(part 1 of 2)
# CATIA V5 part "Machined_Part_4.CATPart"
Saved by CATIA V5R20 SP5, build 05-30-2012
Part number: Macined_Part_4
Source: Unknown
Bounding box of the stored display mesh (mm): x 11486.006 to 11564.501, y -210.178 to 210.176, z 3546.602 to 4547.073
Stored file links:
  C:\Users\rsz0866\Documents\007_CATIA_STEP-Files_and_Test_Models\0001_Machined_Parts_Models\Machined_Part_4.CATPart
  C:\Users\phf1501\Documents\Philshome\LOTAR\LOTAR PMI ASME Data\LOTAR PMI ASME Complex models\LOTAR PMI ASME Complex CATIA Files\LOTAR PMI  ASME Complex CATIA CAD Models\Nacell Support CATIA.CATPart
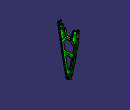
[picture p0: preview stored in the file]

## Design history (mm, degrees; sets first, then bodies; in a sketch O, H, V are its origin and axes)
SpdDefaultsManager1
TTRSSet1
Set1 "MP_4_support"
  DatumSurface1 "OML Surface Section"
  DatumCurve1 "Mid Cutout Sketch"
  DatumCurve2 "Lower Cutout Sketch"
  DatumCurve3 "Main Part Sketch"
  DatumSurface2 "Top cutout surface"
  DatumSurface3 "Top Trim Surface"
  DatumSurface4 "Upper Cutout"
  Plane1: type 2Lines, Element1 edge of DatumCurve1, Element2 edge of DatumCurve2
  Plane2: type 2Lines, Element1 edge of DatumCurve3, Element2 edge of DatumCurve3
  Sketch1 "Center Cutout Sketch" on Plane1, origin (11516.106, 0, 0), H (0, 1, 0), V (0, 0, 1)
    projected line E1 (107.957, 4203.3369) -> (45.82, 4276.09) from edge of DatumCurve1
    projected line E2 (84.7671, 4230.4888) -> (53.4248, 4267.186) from edge of DatumCurve1
    point P1 (107.957, 4203.3369)
    point P2 (45.82, 4276.09)
    projected line E3 (45.82, 4276.09) -> (-45.82, 4276.09) from edge of DatumCurve1
    projected line E4 (34.1105, 4276.09) -> (-34.1105, 4276.09) from edge of DatumCurve1
    point P3 (45.82, 4276.09)
    point P4 (-45.82, 4276.09)
    projected line E5 (-45.82, 4276.09) -> (-107.957, 4203.3369) from edge of DatumCurve1
    projected line E6 (-53.4248, 4267.186) -> (-84.7671, 4230.4888) from edge of DatumCurve1
    point P5 (-45.82, 4276.09)
    point P6 (-107.957, 4203.3369)
    projected curve E7 from edge of DatumCurve1
    projected curve E8 from edge of DatumCurve1
    point P7 (-107.957, 4203.3369)
    point P8 (-82.637, 4059.555)
    projected line E9 (-82.637, 4059.555) -> (82.637, 4059.555) from edge of DatumCurve1
    projected line E10 (-61.4457, 4059.555) -> (61.4457, 4059.555) from edge of DatumCurve1
    point P9 (-82.637, 4059.555)
    point P10 (82.637, 4059.555)
    projected line E11 (67.5561, 3979.545) -> (-67.5561, 3979.545) from edge of DatumCurve2
    projected line E12 (36.6746, 3979.545) -> (-36.6746, 3979.545) from edge of DatumCurve2
    point P11 (67.5561, 3979.545)
    point P12 (-67.5561, 3979.545)
    projected curve E13 from edge of DatumCurve2
    projected curve E14 from edge of DatumCurve2
    point P13 (-67.5561, 3979.545)
    point P14 (-12.3375, 3727.3818)
    projected arc E15 centre (0, 3730.3944) radius 12.7 from (-12.3375, 3727.3818) to (12.3375, 3727.3818) ccw from edge of DatumCurve2
    point P15 (-12.3375, 3727.3818)
    point P16 (12.3375, 3727.3818)
    projected curve E16 from edge of DatumCurve2
    projected curve E17 from edge of DatumCurve2
    point P17 (12.3375, 3727.3818)
    point P18 (67.5561, 3979.545)
    projected curve E18 from edge of DatumCurve1
    projected curve E19 from edge of DatumCurve1
    point P19 (82.637, 4059.555)
    point P20 (107.957, 4203.3369)
    arc A1 centre (-34.1105, 4250.69) radius 25.4 from (-34.1105, 4276.09) to (-53.4248, 4267.186) ccw
    arc A2 centre (-26.8242, 4181.0009) radius 76.2 from (-84.7671, 4230.4888) to (-101.9134, 4168.0377) ccw
    arc A3 centre (-61.4457, 4084.955) radius 25.4 from (-86.4396, 4080.4315) to (-61.4457, 4059.555) ccw
    arc A4 centre (34.1105, 4250.69) radius 25.4 from (34.1105, 4276.09) to (53.4248, 4267.186) cw
    arc A5 centre (26.8242, 4181.0009) radius 76.2 from (84.7671, 4230.4888) to (101.9134, 4168.0377) cw
    arc A6 centre (61.4457, 4084.955) radius 25.4 from (86.4396, 4080.4315) to (61.4457, 4059.555) cw
    arc A7 centre (-36.6746, 3954.145) radius 25.4 from (-36.6746, 3979.545) to (-61.585, 3949.1822) ccw
    arc A8 centre (36.6746, 3954.145) radius 25.4 from (36.6746, 3979.545) to (61.585, 3949.1822) cw
    radius A1 = 25.4
    radius A2 = 76.2
    radius A3 = 25.4
    radius A4 = 25.4
    radius A5 = 76.2
    radius A6 = 25.4
    radius A7 = 25.4
    radius A8 = 25.4
    coincidence: E3 P4, E5 P5, E5 P6, E7 P7, E7 P8, E9 P9, E3 P3, E1 P2, E1 P1, E18 P20, E18 P19, E9 P10, E11 P12, E13 P13, E11 P11, E16 P18, P14 P15, P16 P17
    tangency: A1 E3, A1 E5, A2 E5, A2 E7, A3 E7, A3 E9, A4 E3, A4 E1, A5 E1, A5 E18, A6 E18, A6 E9, A7 E11, A7 E13, A8 E11, A8 E16
  Plane3 "TopPlane": stored without definition
  Offset1 "OML Offset": Offset DatumSurface1, Length 4.318
  Plane4: stored without definition
  Intersect1: ToIntersect1 Plane4, ToIntersect2 DatumSurface3
  Sketch2 "Top Cutout Sketch" on Plane4, origin (279.6175, -1557.6443, -217.9088), H (-0.9843, -0.1767, 0), V (0.0241, -0.1343, 0.9907)
    projected line E1 (-11301.8201, 4764.6026) -> (-11197.9018, 4758.5452) from edge of Intersect1
    projected line E2 (-11405.6729, 4775.6542) -> (-11301.8201, 4764.6026) from edge of Intersect1
    line L1 (-11197.9018, 4758.5452) -> (-11195.8601, 4817.9404)
    line L2 (-11195.8601, 4817.9404) -> (-11399.9073, 4829.8343)
    line L3 (-11399.9073, 4829.8343) -> (-11405.6729, 4775.6542)
    parallelism: L2 E1
    perpendicularity: L3 E2
  Fill1: Boundary Sketch2
  DatumSurface5 "Inside top trim Surface"
Set2 "Hole Support"
  Line1 "AFPO_GROUNDING_FASTENER_FV3": stored without definition
  Line2 "FFPO_FV57": stored without definition
  Line3 "AFPO_GROUNDING_FASTENER_FV2": stored without definition
  Line4 "FFPO_FV58": stored without definition
  Line5 "AFPO_FV45": stored without definition
  Line6 "FFPO_FV59": stored without definition
  Line7 "FFPO_GROUNDING_FASTENER_FV2": stored without definition
  Line8 "AFPO_FV44": stored without definition
  Line9 "AFPO_FV43": stored without definition
  Line10 "FFPO_FV60": stored without definition
  Line11 "AFPO_FV42": stored without definition
  Line12 "FFPO_FV61": stored without definition
  Line13 "AFPO_FV41": stored without definition
  Line14 "FFPO_FV62": stored without definition
  Line15 "AFPO_FV40": stored without definition
  Line16 "FFPO_FV63": stored without definition
  Line17 "AFPO_FV39": stored without definition
  Line18 "FFPO_FV64": stored without definition
  Line19 "FFPO_FV65": stored without definition
  Line20 "AFPO_FV38": stored without definition
  Line21 "AFPO_FV37": stored without definition
  Line22 "FFPO_FV66": stored without definition
  Line23 "AFPO_FV36": stored without definition
  Line24 "FFPO_FV67": stored without definition
  Line25 "FFPO_FV68": stored without definition
  Line26 "AFPO_FV35": stored without definition
  Line27 "AFPO_FV34": stored without definition
  Line28 "FFPO_FV69": stored without definition
  Line29 "AFPO_FV33": stored without definition
  Line30 "FFPO_FV70": stored without definition
  Line31 "FFPO_FV71": stored without definition
  Line32 "AFPO_FV32": stored without definition
  Line33 "AFPO_GROUNDING_FASTENER_FV1": stored without definition
  Line34 "FFPO_FV72": stored without definition
  Line35 "FFPO_FV73": stored without definition
  Line36 "AFPO_FV31": stored without definition
  Line37 "AFPO_FV30": stored without definition
  Line38 "FFPO_FV74": stored without definition
  Line39 "FFPO_FV75": stored without definition
  Line40 to Line78: stored without definition
  Point1 to Point6: stored without definition
  Point7 "Result of Point_6 Fastener Posn Frame 5": stored without definition
  Point8 "Result of Point_5 Fastener Posn Frame 5": stored without definition
Set3 "Pocket stuff"
  DatumSurface6 "Pocket 1 Surface"
  DatumSurface7 "Pocket 2 Surface"
  DatumSurface8 "Pocket 3 Surface"
  DatumSurface9 "Pocket 6 Surface"
  DatumSurface10 "Pocket 8 Surface"
  DatumSurface11 "Pocket 9 Surface"
  DatumSurface12 "Pocket 10 Surface"
  DatumSurface13 "Pocket 11 Surface"
  DatumSurface14 "Pocket 12 Surface"
  DatumSurface15 "Pocket 4 Surface"
  DatumSurface16 "Pocket 5 Surface"
  DatumSurface17 "Pocket 7 Surface"
  DatumSurface18 "Pocket 14 Surface"
Body1 "MP_4_Geo" (main body)
  Pad1: profile DatumCurve3, length 254
  Split1: SplitPlane Offset1
  Split2: SplitPlane DatumSurface2
  Split3: SplitPlane DatumSurface4
  Split4: SplitPlane Plane3
  Pocket1: profile Sketch2, direction (0.175, -0.9751, -0.1364), length 254
  Split5: SplitPlane DatumSurface5
  Mirror1: of the body so far, about Plane2
  Split6: SplitPlane DatumSurface6
  Split7: SplitPlane DatumSurface7
  Split8: SplitPlane DatumSurface8
  Split9: SplitPlane DatumSurface9
  Split10: SplitPlane DatumSurface10
  Split11: SplitPlane DatumSurface11
  Split12: SplitPlane DatumSurface12
  Split13: SplitPlane DatumSurface13
  Fillet1: radius 20.32, on edge [face of Split3 | face of Split3]
  Fillet2: radius 20.32, on edge [face of Mirror1 | face of Mirror1]
  Split14: SplitPlane DatumSurface14
  Fillet3: radius 12.7, on edge [face of Pad1 | face of Mirror1]
  Fillet4: radius 12.7, on edge [face of Split5 | face of Pad1]
  Sketch3 on face of Split5, origin (0, -1117.5755, 4170.8484), H (1, 0, 0), V (0, 0.9659, 0.2588)
    projected curve E1 from edge [face of Split5 | face of Fillet4]
    projected arc E2 centre (4993.4686, 38646.5585) radius 38209.305 from (11496.5567, 994.7214) to (11514.5486, 997.8334) ccw from edge [face of Split5 | face of Split5]
    projected line E3 (11514.5486, 997.8334) -> (11514.5486, 1057.402) from edge [face of Split5 | face of Split5]
    projected line E4 (11486.007, 1057.402) -> (11514.5486, 1057.402) from edge [face of Split5 | face of Split2]
    projected line E5 (11486.007, 1057.402) -> (11486.007, 982.1378) from edge [face of Pad1 | face of Split5]
  Pad2: profile Sketch3, direction (0, -0.2588, 0.9659), length 2.54
  Split15: SplitPlane DatumSurface16
  Split16: SplitPlane DatumSurface17
  Sketch4 on face of Mirror1, origin (0, 1117.5755, 4170.8484), H (-1, 0, 0), V (0, -0.9659, 0.2588)
    projected line E1 (-11486.007, 1057.402) -> (-11514.5486, 1057.402) from edge [face of Mirror1 | face of Mirror1]
    projected line E2 (-11514.5486, 997.8334) -> (-11514.5486, 1057.402) from edge [face of Mirror1 | face of Mirror1]
    projected arc E3 centre (-4993.4686, 38646.5585) radius 38209.305 from (-11514.5486, 997.8334) to (-11496.5567, 994.7214) ccw from edge [face of Mirror1 | face of Mirror1]
    projected curve E4 from edge [face of Mirror1 | face of Fillet3]
    projected line E5 (-11486.007, 982.1378) -> (-11486.007, 1057.402) from edge [face of Pad2 | face of Mirror1]
  Pad3: profile Sketch4, direction (0, 0.2588, 0.9659), length 2.54
  Split17: SplitPlane DatumSurface15
  Body2
    CloseSurface1: CloseElement DatumSurface18
  Remove1: tool Body2
  Pocket2: profile Sketch1, direction (-1, 0, 0), through (limit type 6)
  Sketch5 on {plane type Tangent, Support face of Split1, RefPoint {point type OnSurface, Support face of Split1, RefPoint {point stored without definition}, Length 0, Direction (0, -143.1131, 989.7063)}}, origin (11533.5155, -199.7821, 4491.7645), H (0.9848, 0.1721, 0.0249), V (0, 0.1431, -0.9897)
    point P1 (0, 0)
    intersected point E1 (0, 0) from Line1
    coincidence: E1 P1
  Hole1: placed by Sketch5, at (11533.5155, -199.7821, 4491.7645) direction (0.1739, -0.9746, -0.1409), diameter 9.2964, through (limit type 6)
  Sketch6 on {plane type Tangent, Support face of Split1, RefPoint {point type OnSurface, Support face of Split1, RefPoint {point stored without definition}, Length 0, Direction (0, -151.3494, 988.4803)}}, origin (11533.5335, -193.266, 4448.0114), H (0.9852, 0.1695, 0.026), V (0, 0.1513, -0.9885)
    point P1 (0, 0)
    intersected point E1 (0, 0) from Line3
    coincidence: E1 P1
  Hole2: placed by Sketch6, at (11533.5335, -193.266, 4448.0114) direction (0.1715, -0.9738, -0.1491), diameter 9.2964, through (limit type 6)
  Sketch7 on {plane type Tangent, Support face of Split1, RefPoint {point type OnSurface, Support face of Split1, RefPoint {point stored without definition}, Length 0, Direction (0, -163.5309, 986.5382)}}, origin (11500.5108, -181.5879, 4340.9463), H (0.9864, 0.1623, 0.0269), V (0, 0.1635, -0.9865)
    point P1 (0, 0)
    intersected point E1 (0, 0) from Line7
    coincidence: E1 P1
  Hole3: placed by Sketch7, at (11500.5108, -181.5879, 4340.9463) direction (0.1645, -0.9731, -0.1613), diameter 9.2964, through (limit type 6)
  Sketch8 on {plane type Tangent, Support face of Split1, RefPoint {point type OnSurface, Support face of Split1, RefPoint {point stored without definition}, Length 0, Direction (0, -241.454, 970.4123)}}, origin (11533.7779, -50.159, 3696.5006), H (0.9907, 0.1319, 0.0328), V (0, 0.2415, -0.9704)
    point P1 (0, 0)
    intersected point E1 (0, 0) from Line33
    coincidence: E1 P1
  Hole4: placed by Sketch8, at (11533.7779, -50.159, 3696.5006) direction (0.1359, -0.9614, -0.2392), diameter 9.2964, through (limit type 6)
  Sketch9 on {plane type Tangent, Support face of Mirror1, RefPoint {point type OnSurface, Support face of Mirror1, RefPoint {point stored without definition}, Length 0, Direction (0, -241.454, -970.4123)}}, origin (11533.7779, 50.159, 3696.5006), H (0.9907, -0.1319, 0.0328), V (0, 0.2415, 0.9704)
    point P1 (0, 0)
    intersected point E1 (0, 0) from Line46
    coincidence: E1 P1
  Hole5: placed by Sketch9, at (11533.7779, 50.159, 3696.5006) direction (0.1359, 0.9614, -0.2392), diameter 9.2964, through (limit type 6)
  Sketch10 on {plane type Tangent, Support face of Mirror1, RefPoint {point type OnSurface, Support face of Mirror1, RefPoint {point stored without definition}, Length 0, Direction (0, -163.5309, -986.5382)}}, origin (11500.5108, 181.5879, 4340.9463), H (0.9864, -0.1623, 0.0269), V (0, 0.1635, 0.9865)
    point P1 (0, 0)
    intersected point E1 (0, 0) from Line72
    coincidence: E1 P1
  Hole6: placed by Sketch10, at (11500.5108, 181.5879, 4340.9463) direction (0.1645, 0.9731, -0.1613), diameter 9.2964, through (limit type 6)
  Sketch11 on {plane type Tangent, Support face of Mirror1, RefPoint {point type OnSurface, Support face of Mirror1, RefPoint {point stored without definition}, Length 0, Direction (0, -143.1131, -989.7063)}}, origin (11533.5155, 199.7821, 4491.7645), H (0.9848, -0.1721, 0.0249), V (0, 0.1431, 0.9897)
    point P1 (0, 0)
    intersected point E1 (0, 0) from Line78
    coincidence: E1 P1
  Hole7: placed by Sketch11, at (11533.5155, 199.7821, 4491.7645) direction (0.1739, 0.9746, -0.1409), diameter 9.2964, through (limit type 6)
  Sketch12 on {plane type Tangent, Support face of Mirror1, RefPoint {point type OnSurface, Support face of Mirror1, RefPoint {point stored without definition}, Length 0, Direction (0, -151.3494, -988.4803)}}, origin (11533.5335, 193.266, 4448.0114), H (0.9852, -0.1695, 0.026), V (0, 0.1513, 0.9885)
    point P1 (0, 0)
    intersected point E1 (0, 0) from Line76
    coincidence: E1 P1
  Hole8: placed by Sketch12, at (11533.5335, 193.266, 4448.0114) direction (0.1715, 0.9738, -0.1491), diameter 9.2964, through (limit type 6)
  Sketch13 on face of Split4, origin (11535.2251, -184.7373, 4542.8709), H (0.9967, -0.0122, 0.0803), V (0, 0.9887, 0.1496)
    point P1 (0, 0)
    reference projected point E1 (0, 0) from Point1
    coincidence: E1 P1
  Hole9: placed by Sketch13, at (11535.2251, -184.7373, 4542.8709) direction (0.0812, 0.1492, -0.9855), diameter 6.3119, through (limit type 6)
  Sketch14 on face of Split4, origin (11500.0357, -190.5727, 4539.088), H (0.9967, -0.0122, 0.0803), V (0, 0.9887, 0.1496)
    point P1 (0, 0)
    reference projected point E1 (0, 0) from Point2
    coincidence: E1 P1
  Hole10: placed by Sketch14, at (11500.0357, -190.5727, 4539.088) direction (0.0812, 0.1492, -0.9855), diameter 6.3119, through (limit type 6)
  Sketch15 on face of Mirror1, origin (11535.2251, 184.7373, 4542.8709), H (0.9967, 0.0122, 0.0803), V (0, 0.9887, -0.1496)
    point P1 (0, 0)
    reference projected point E1 (0, 0) from Point4
    coincidence: E1 P1
  Hole11: placed by Sketch15, at (11535.2251, 184.7373, 4542.8709) direction (0.0812, -0.1492, -0.9855), diameter 6.3119, through (limit type 6)
  Sketch16 on face of Mirror1, origin (11500.0357, 190.5727, 4539.088), H (0.9967, 0.0122, 0.0803), V (0, 0.9887, -0.1496)
    point P1 (0, 0)
    reference projected point E1 (0, 0) from Point3
    coincidence: E1 P1
  Hole12: placed by Sketch16, at (11500.0357, 190.5727, 4539.088) direction (0.0812, -0.1492, -0.9855), diameter 6.3119, through (limit type 6)
  Sketch17 on face of Split9, origin (11516.106, -120.65, 4318), H (0, 1, 0), V (0, 0, -1)
    point P1 (0, 0)
    reference projected point E1 (0, 0) from Point5
    coincidence: E1 P1
  Hole13: placed by Sketch17, at (11516.106, -120.65, 4318) direction (1, 0, 0), diameter 6.4008, through (limit type 6)
  Sketch18 on face of Split8, origin (11516.106, 120.65, 4318), H (0, 1, 0), V (0, 0, -1)
    point P1 (0, 0)
    reference projected point E1 (0, 0) from Point6
    coincidence: E1 P1
  Hole14: placed by Sketch18, at (11516.106, 120.65, 4318) direction (1, 0, 0), diameter 6.4008, through (limit type 6)
  Sketch19 on {plane type Tangent, Support face of Split1, RefPoint {point type OnSurface, Support face of Split1, RefPoint {point stored without definition}, Length 0, Direction (0, -144.9294, 989.442)}}, origin (11500.4992, -205.5404, 4490.9343), H (0.9849, 0.1713, 0.0251), V (0, 0.1449, -0.9894)
    point P1 (0, 0)
    intersected point E1 (0, 0) from Line2
    coincidence: E1 P1
  Hole15: placed by Sketch19, at (11500.4992, -205.5404, 4490.9343) direction (0.1732, -0.9745, -0.1427), diameter 7.7089, through (limit type 6)
  Sketch20 on {plane type Tangent, Support face of Split1, RefPoint {point type OnSurface, Support face of Split1, RefPoint {point stored without definition}, Length 0, Direction (0, -153.3155, 988.1773)}}, origin (11500.5026, -198.9361, 4447.1461), H (0.9853, 0.1687, 0.0262), V (0, 0.1533, -0.9882)
    point P1 (0, 0)
    intersected point E1 (0, 0) from Line4
    coincidence: E1 P1
  Hole16: placed by Sketch20, at (11500.5026, -198.9361, 4447.1461) direction (0.1707, -0.9737, -0.1511), diameter 7.7089, through (limit type 6)
  Sketch21 on {plane type Tangent, Support face of Split1, RefPoint {point type OnSurface, Support face of Split1, RefPoint {point stored without definition}, Length 0, Direction (0, -161.8829, 986.81)}}, origin (11533.5577, -184.3459, 4391.7892), H (0.9858, 0.1658, 0.0272), V (0, 0.1619, -0.9868)
    point P1 (0, 0)
    intersected point E1 (0, 0) from Line5
    coincidence: E1 P1
  Hole17: placed by Sketch21, at (11533.5577, -184.3459, 4391.7892) direction (0.168, -0.9728, -0.1596), diameter 7.7089, through (limit type 6)
  Sketch22 on {plane type Tangent, Support face of Split1, RefPoint {point type OnSurface, Support face of Split1, RefPoint {point stored without definition}, Length 0, Direction (0, -164.041, 986.4535)}}, origin (11500.5075, -189.8922, 4390.8825), H (0.9859, 0.165, 0.0274), V (0, 0.164, -0.9865)
    point P1 (0, 0)
    intersected point E1 (0, 0) from Line6
    coincidence: E1 P1
  Hole18: placed by Sketch22, at (11500.5075, -189.8922, 4390.8825) direction (0.1672, -0.9726, -0.1617), diameter 7.7089, through (limit type 6)
  Sketch23 on {plane type Tangent, Support face of Split1, RefPoint {point type OnSurface, Support face of Split1, RefPoint {point stored without definition}, Length 0, Direction (0, -161.7931, 986.8247)}}, origin (11533.5778, -176.1335, 4341.8382), H (0.9863, 0.1631, 0.0267), V (0, 0.1618, -0.9868)
    point P1 (0, 0)
    intersected point E1 (0, 0) from Line8
    coincidence: E1 P1
  Hole19: placed by Sketch23, at (11533.5778, -176.1335, 4341.8382) direction (0.1652, -0.9733, -0.1596), diameter 7.7089, through (limit type 6)
  Sketch24 on {plane type Tangent, Support face of Split1, RefPoint {point type OnSurface, Support face of Split1, RefPoint {point stored without definition}, Length 0, Direction (0, -162.7597, 986.6657)}}, origin (11533.5954, -167.9242, 4291.8914), H (0.9867, 0.1606, 0.0265), V (0, 0.1628, -0.9867)
    point P1 (0, 0)
    intersected point E1 (0, 0) from Line9
    coincidence: E1 P1
  Hole20: placed by Sketch24, at (11533.5954, -167.9242, 4291.8914) direction (0.1628, -0.9735, -0.1606), diameter 7.7089, through (limit type 6)
  Sketch25 on {plane type Tangent, Support face of Split1, RefPoint {point type OnSurface, Support face of Split1, RefPoint {point stored without definition}, Length 0, Direction (0, -164.3356, 986.4045)}}, origin (11500.517, -173.296, 4291.0077), H (0.9868, 0.1598, 0.0266), V (0, 0.1643, -0.9864)
    point P1 (0, 0)
    intersected point E1 (0, 0) from Line10
    coincidence: E1 P1
  Hole21: placed by Sketch25, at (11500.517, -173.296, 4291.0077) direction (0.162, -0.9734, -0.1622), diameter 7.7089, through (limit type 6)
  Sketch26 on {plane type Tangent, Support face of Split1, RefPoint {point type OnSurface, Support face of Split1, RefPoint {point stored without definition}, Length 0, Direction (0, -165.1506, 986.2684)}}, origin (11533.6115, -159.6283, 4241.9652), H (0.987, 0.1583, 0.0265), V (0, 0.1652, -0.9863)
    point P1 (0, 0)
    intersected point E1 (0, 0) from Line11
    coincidence: E1 P1
  Hole22: placed by Sketch26, at (11533.6115, -159.6283, 4241.9652) direction (0.1605, -0.9735, -0.163), diameter 7.7089, through (limit type 6)
  Sketch27 on {plane type Tangent, Support face of Split1, RefPoint {point type OnSurface, Support face of Split1, RefPoint {point stored without definition}, Length 0, Direction (0, -166.6142, 986.0222)}}, origin (11500.5186, -164.9233, 4241.0796), H (0.9872, 0.1575, 0.0266), V (0, 0.1666, -0.986)
    point P1 (0, 0)
    intersected point E1 (0, 0) from Line12
    coincidence: E1 P1
  Hole23: placed by Sketch27, at (11500.5186, -164.9233, 4241.0796) direction (0.1598, -0.9734, -0.1645), diameter 7.7089, through (limit type 6)
  Sketch28 on {plane type Tangent, Support face of Split1, RefPoint {point type OnSurface, Support face of Split1, RefPoint {point stored without definition}, Length 0, Direction (0, -168.4055, 985.7178)}}, origin (11533.6259, -151.1888, 4192.0667), H (0.9874, 0.1561, 0.0267), V (0, 0.1684, -0.9857)
    point P1 (0, 0)
    intersected point E1 (0, 0) from Line13
    coincidence: E1 P1
  Hole24: placed by Sketch28, at (11533.6259, -151.1888, 4192.0667) direction (0.1584, -0.9733, -0.1663), diameter 7.7089, through (limit type 6)
  Sketch29 on {plane type Tangent, Support face of Split1, RefPoint {point type OnSurface, Support face of Split1, RefPoint {point stored without definition}, Length 0, Direction (0, -169.7864, 985.4809)}}, origin (11500.5223, -156.4103, 4191.1734), H (0.9875, 0.1554, 0.0268), V (0, 0.1698, -0.9855)
    point P1 (0, 0)
    intersected point E1 (0, 0) from Line14
    coincidence: E1 P1
  Hole25: placed by Sketch29, at (11500.5223, -156.4103, 4191.1734) direction (0.1577, -0.9732, -0.1677), diameter 7.7089, through (limit type 6)
  Sketch30 on {plane type Tangent, Support face of Split1, RefPoint {point type OnSurface, Support face of Split1, RefPoint {point stored without definition}, Length 0, Direction (0, -172.2768, 985.0486)}}, origin (11533.6404, -142.5689, 4142.202), H (0.9877, 0.154, 0.0269), V (0, 0.1723, -0.985)
    point P1 (0, 0)
    intersected point E1 (0, 0) from Line15
    coincidence: E1 P1
  Hole26: placed by Sketch30, at (11533.6404, -142.5689, 4142.202) direction (0.1563, -0.9729, -0.1702), diameter 7.7089, through (limit type 6)
  Sketch31 on {plane type Tangent, Support face of Split1, RefPoint {point type OnSurface, Support face of Split1, RefPoint {point stored without definition}, Length 0, Direction (0, -173.5999, 984.8163)}}, origin (11500.5259, -147.7209, 4141.3035), H (0.9878, 0.1533, 0.027), V (0, 0.1736, -0.9848)
    point P1 (0, 0)
    intersected point E1 (0, 0) from Line16
    coincidence: E1 P1
  Hole27: placed by Sketch31, at (11500.5259, -147.7209, 4141.3035) direction (0.1556, -0.9728, -0.1715), diameter 7.7089, through (limit type 6)
  Sketch32 on {plane type Tangent, Support face of Split1, RefPoint {point type OnSurface, Support face of Split1, RefPoint {point stored without definition}, Length 0, Direction (0, -176.7535, 984.2552)}}, origin (11533.6539, -133.7389, 4092.3767), H (0.988, 0.152, 0.0273), V (0, 0.1768, -0.9843)
    point P1 (0, 0)
    intersected point E1 (0, 0) from Line17
    coincidence: E1 P1
  Hole28: placed by Sketch32, at (11533.6539, -133.7389, 4092.3767) direction (0.1544, -0.9725, -0.1746), diameter 7.7089, through (limit type 6)
  Sketch33 on {plane type Tangent, Support face of Split1, RefPoint {point type OnSurface, Support face of Split1, RefPoint {point stored without definition}, Length 0, Direction (0, -178.0476, 984.0219)}}, origin (11500.5286, -138.8222, 4091.4663), H (0.9881, 0.1512, 0.0274), V (0, 0.178, -0.984)
    point P1 (0, 0)
    intersected point E1 (0, 0) from Line18
    coincidence: E1 P1
  Hole29: placed by Sketch33, at (11500.5286, -138.8222, 4091.4663) direction (0.1537, -0.9723, -0.1759), diameter 7.7089, through (limit type 6)
  Sketch34 on {plane type Tangent, Support face of Split1, RefPoint {point type OnSurface, Support face of Split1, RefPoint {point stored without definition}, Length 0, Direction (0, -183.284, 983.06)}}, origin (11500.5328, -129.6785, 4041.6701), H (0.9884, 0.1492, 0.0278), V (0, 0.1833, -0.9831)
    point P1 (0, 0)
    intersected point E1 (0, 0) from Line19
    coincidence: E1 P1
  Hole30: placed by Sketch34, at (11500.5328, -129.6785, 4041.6701) direction (0.1518, -0.9717, -0.1812), diameter 7.7089, through (limit type 6)
  Sketch35 on {plane type Tangent, Support face of Split1, RefPoint {point type OnSurface, Support face of Split1, RefPoint {point stored without definition}, Length 0, Direction (0, -181.9836, 983.3016)}}, origin (11533.6674, -124.6646, 4042.5986), H (0.9883, 0.1499, 0.0277), V (0, 0.182, -0.9833)
    point P1 (0, 0)
    intersected point E1 (0, 0) from Line20
    coincidence: E1 P1
  Hole31: placed by Sketch35, at (11533.6674, -124.6646, 4042.5986) direction (0.1524, -0.9718, -0.1799), diameter 7.7089, through (limit type 6)
  Sketch36 on {plane type Tangent, Support face of Split1, RefPoint {point type OnSurface, Support face of Split1, RefPoint {point stored without definition}, Length 0, Direction (0, -188.2022, 982.1303)}}, origin (11533.6814, -115.3027, 3992.8785), H (0.9886, 0.1478, 0.0283), V (0, 0.1882, -0.9821)
    point P1 (0, 0)
    intersected point E1 (0, 0) from Line21
    coincidence: E1 P1
  Hole32: placed by Sketch36, at (11533.6814, -115.3027, 3992.8785) direction (0.1504, -0.971, -0.1861), diameter 7.7089, through (limit type 6)
  Sketch37 on {plane type Tangent, Support face of Split1, RefPoint {point type OnSurface, Support face of Split1, RefPoint {point stored without definition}, Length 0, Direction (0, -189.4221, 981.8957)}}, origin (11500.5367, -120.4291, 3992.8835), H (0.9887, 0.1471, 0.0284), V (0, 0.1894, -0.9819)
    point P1 (0, 0)
    intersected point E1 (0, 0) from Line22
    coincidence: E1 P1
  Hole33: placed by Sketch37, at (11500.5367, -120.4291, 3992.8835) direction (0.1498, -0.9708, -0.1873), diameter 7.7089, through (limit type 6)
  Sketch38 on {plane type Tangent, Support face of Split1, RefPoint {point type OnSurface, Support face of Split1, RefPoint {point stored without definition}, Length 0, Direction (0, -195.6636, 980.6711)}}, origin (11533.6954, -105.5966, 3943.2297), H (0.9889, 0.1455, 0.029), V (0, 0.1957, -0.9807)
    point P1 (0, 0)
    intersected point E1 (0, 0) from Line23
    coincidence: E1 P1
  Hole34: placed by Sketch38, at (11533.6954, -105.5966, 3943.2297) direction (0.1483, -0.9698, -0.1935), diameter 7.7089, through (limit type 6)
  Sketch39 on {plane type Tangent, Support face of Split1, RefPoint {point type OnSurface, Support face of Split1, RefPoint {point stored without definition}, Length 0, Direction (0, -196.4609, 980.5117)}}, origin (11500.5392, -111.257, 3946.2153), H (0.989, 0.145, 0.029), V (0, 0.1965, -0.9805)
    point P1 (0, 0)
    intersected point E1 (0, 0) from Line24
    coincidence: E1 P1
  Hole35: placed by Sketch39, at (11500.5392, -111.257, 3946.2153) direction (0.1479, -0.9697, -0.1943), diameter 7.7089, through (limit type 6)
  Sketch40 on {plane type Tangent, Support face of Split1, RefPoint {point type OnSurface, Support face of Split1, RefPoint {point stored without definition}, Length 0, Direction (0, -204.5244, 978.8615)}}, origin (11533.7109, -95.4795, 3893.6695), H (0.9893, 0.1429, 0.0299), V (0, 0.2045, -0.9789)
    point P1 (0, 0)
    intersected point E1 (0, 0) from Line26
    coincidence: E1 P1
  Hole36: placed by Sketch40, at (11533.7109, -95.4795, 3893.6695) direction (0.146, -0.9684, -0.2023), diameter 7.7089, through (limit type 6)
  Sketch41 on {plane type Tangent, Support face of Split1, RefPoint {point type OnSurface, Support face of Split1, RefPoint {point stored without definition}, Length 0, Direction (0, -204.7685, 978.8104)}}, origin (11500.5433, -101.7214, 3899.6256), H (0.9893, 0.1426, 0.0298), V (0, 0.2048, -0.9788)
    point P1 (0, 0)
    intersected point E1 (0, 0) from Line25
    coincidence: E1 P1
  Hole37: placed by Sketch41, at (11500.5433, -101.7214, 3899.6256) direction (0.1457, -0.9684, -0.2026), diameter 7.7089, through (limit type 6)
  Sketch42 on {plane type Tangent, Support face of Split1, RefPoint {point type OnSurface, Support face of Split1, RefPoint {point stored without definition}, Length 0, Direction (0, -214.7234, 976.6749)}}, origin (11533.7295, -84.8777, 3844.2167), H (0.9897, 0.1401, 0.0308), V (0, 0.2147, -0.9767)
    point P1 (0, 0)
    intersected point E1 (0, 0) from Line27
    coincidence: E1 P1
  Hole38: placed by Sketch42, at (11533.7295, -84.8777, 3844.2167) direction (0.1435, -0.9666, -0.2125), diameter 7.7089, through (limit type 6)
  Sketch43 on {plane type Tangent, Support face of Split1, RefPoint {point type OnSurface, Support face of Split1, RefPoint {point stored without definition}, Length 0, Direction (0, -214.3624, 976.7542)}}, origin (11500.5481, -91.7591, 3853.1309), H (0.9897, 0.14, 0.0307), V (0, 0.2144, -0.9768)
    point P1 (0, 0)
    intersected point E1 (0, 0) from Line28
    coincidence: E1 P1
  Hole39: placed by Sketch43, at (11500.5481, -91.7591, 3853.1309) direction (0.1434, -0.9667, -0.2121), diameter 7.7089, through (limit type 6)
  Sketch44 on {plane type Tangent, Support face of Split1, RefPoint {point type OnSurface, Support face of Split1, RefPoint {point stored without definition}, Length 0, Direction (0, -224.7151, 974.4245)}}, origin (11533.7466, -73.7581, 3794.8771), H (0.99, 0.1372, 0.0316), V (0, 0.2247, -0.9744)
    point P1 (0, 0)
    intersected point E1 (0, 0) from Line29
    coincidence: E1 P1
  Hole40: placed by Sketch44, at (11533.7466, -73.7581, 3794.8771) direction (0.1408, -0.9647, -0.2225), diameter 7.7089, through (limit type 6)
  Sketch45 on {plane type Tangent, Support face of Split1, RefPoint {point type OnSurface, Support face of Split1, RefPoint {point stored without definition}, Length 0, Direction (0, -223.9493, 974.6008)}}, origin (11500.5521, -81.3346, 3806.738), H (0.99, 0.1373, 0.0316), V (0, 0.2239, -0.9746)
    point P1 (0, 0)
    intersected point E1 (0, 0) from Line30
    coincidence: E1 P1
  Hole41: placed by Sketch45, at (11500.5521, -81.3346, 3806.738) direction (0.1409, -0.9649, -0.2217), diameter 7.7089, through (limit type 6)
  Sketch46 on {plane type Tangent, Support face of Split1, RefPoint {point type OnSurface, Support face of Split1, RefPoint {point stored without definition}, Length 0, Direction (0, -233.3083, 972.4028)}}, origin (11533.7634, -62.1656, 3745.6401), H (0.9904, 0.1344, 0.0323), V (0, 0.2333, -0.9724)
    point P1 (0, 0)
    intersected point E1 (0, 0) from Line32
    coincidence: E1 P1
  Hole42: placed by Sketch46, at (11533.7634, -62.1656, 3745.6401) direction (0.1382, -0.9631, -0.2311), diameter 7.7089, through (limit type 6)
  Sketch47 on {plane type Tangent, Support face of Split1, RefPoint {point type OnSurface, Support face of Split1, RefPoint {point stored without definition}, Length 0, Direction (0, -232.2993, 972.6444)}}, origin (11500.5561, -70.4796, 3760.4384), H (0.9904, 0.1348, 0.0322), V (0, 0.2323, -0.9726)
    point P1 (0, 0)
    intersected point E1 (0, 0) from Line31
    coincidence: E1 P1
  Hole43: placed by Sketch47, at (11500.5561, -70.4796, 3760.4384) direction (0.1385, -0.9633, -0.2301), diameter 7.7089, through (limit type 6)
  Sketch48 on {plane type Tangent, Support face of Split1, RefPoint {point type OnSurface, Support face of Split1, RefPoint {point stored without definition}, Length 0, Direction (0, -239.7025, 970.8464)}}, origin (11500.5607, -59.2543, 3714.2229), H (0.9907, 0.1324, 0.0327), V (0, 0.2397, -0.9708)
    point P1 (0, 0)
    intersected point E1 (0, 0) from Line34
    coincidence: E1 P1
  Hole44: placed by Sketch48, at (11500.5607, -59.2543, 3714.2229) direction (0.1364, -0.9618, -0.2375), diameter 7.7089, through (limit type 6)
  Sketch49 on {plane type Tangent, Support face of Split1, RefPoint {point type OnSurface, Support face of Split1, RefPoint {point stored without definition}, Length 0, Direction (0, -248.3602, 968.6678)}}, origin (11500.5648, -47.6608, 3668.1043), H (0.9909, 0.1302, 0.0334), V (0, 0.2484, -0.9687)
    point P1 (0, 0)
    intersected point E1 (0, 0) from Line35
    coincidence: E1 P1
  Hole45: placed by Sketch49, at (11500.5648, -47.6608, 3668.1043) direction (0.1344, -0.9599, -0.2461), diameter 7.7089, through (limit type 6)
  Sketch50 on {plane type Tangent, Support face of Split1, RefPoint {point type OnSurface, Support face of Split1, RefPoint {point stored without definition}, Length 0, Direction (0, -251.4453, 967.8715)}}, origin (11533.7929, -37.6908, 3647.4847), H (0.991, 0.1295, 0.0336), V (0, 0.2514, -0.9679)
    point P1 (0, 0)
    intersected point E1 (0, 0) from Line36
    coincidence: E1 P1
  Hole46: placed by Sketch50, at (11533.7929, -37.6908, 3647.4847) direction (0.1338, -0.9592, -0.2492), diameter 7.7089, through (limit type 6)
  Sketch51 on {plane type Tangent, Support face of Split1, RefPoint {point type OnSurface, Support face of Split1, RefPoint {point stored without definition}, Length 0, Direction (0, -251.0059, 967.9856)}}, origin (11500.5667, -35.7169, 3622.0475), H (0.991, 0.1292, 0.0335), V (0, 0.251, -0.968)
    point P1 (0, 0)
    intersected point E1 (0, 0) from Line38
    coincidence: E1 P1
  Hole47: placed by Sketch51, at (11500.5667, -35.7169, 3622.0475) direction (0.1335, -0.9593, -0.2488), diameter 7.7089, through (limit type 6)
  Sketch52 on {plane type Tangent, Support face of Split1, RefPoint {point type OnSurface, Support face of Split1, RefPoint {point stored without definition}, Length 0, Direction (0, -249.9188, 968.2668)}}, origin (11533.7956, -24.9971, 3598.474), H (0.9911, 0.1291, 0.0333), V (0, 0.2499, -0.9683)
    point P1 (0, 0)
    intersected point E1 (0, 0) from Line37
    coincidence: E1 P1
  Hole48: placed by Sketch52, at (11533.7956, -24.9971, 3598.474) direction (0.1333, -0.9596, -0.2477), diameter 7.7089, through (limit type 6)
  Sketch53 on {plane type Tangent, Support face of Split1, RefPoint {point type OnSurface, Support face of Split1, RefPoint {point stored without definition}, Length 0, Direction (0, -249.4488, 968.388)}}, origin (11500.5675, -23.8047, 3575.9634), H (0.9911, 0.1289, 0.0332), V (0, 0.2494, -0.9684)
    point P1 (0, 0)
    intersected point E1 (0, 0) from Line39
    coincidence: E1 P1
  Hole49: placed by Sketch53, at (11500.5675, -23.8047, 3575.9634) direction (0.1331, -0.9598, -0.2472), diameter 7.7089, through (limit type 6)
  Sketch54 on {plane type Tangent, Support face of Mirror1, RefPoint {point type OnSurface, Support face of Mirror1, RefPoint {point stored without definition}, Length 0, Direction (0, -249.4488, -968.388)}}, origin (11500.5675, 23.8047, 3575.9634), H (0.9911, -0.1289, 0.0332), V (0, 0.2494, 0.9684)
    point P1 (0, 0)
    intersected point E1 (0, 0) from Line40
    coincidence: E1 P1
  Hole50: placed by Sketch54, at (11500.5675, 23.8047, 3575.9634) direction (0.1331, 0.9598, -0.2472), diameter 7.7089, through (limit type 6)
  Sketch55 on {plane type Tangent, Support face of Mirror1, RefPoint {point type OnSurface, Support face of Mirror1, RefPoint {point stored without definition}, Length 0, Direction (0, -249.9188, -968.2668)}}, origin (11533.7956, 24.9971, 3598.474), H (0.9911, -0.1291, 0.0333), V (0, 0.2499, 0.9683)
    point P1 (0, 0)
    intersected point E1 (0, 0) from Line42
    coincidence: E1 P1
  Hole51: placed by Sketch55, at (11533.7956, 24.9971, 3598.474) direction (0.1333, 0.9596, -0.2477), diameter 7.7089, through (limit type 6)
  Sketch56 on {plane type Tangent, Support face of Mirror1, RefPoint {point type OnSurface, Support face of Mirror1, RefPoint {point stored without definition}, Length 0, Direction (0, -251.0059, -967.9856)}}, origin (11500.5667, 35.7169, 3622.0475), H (0.991, -0.1292, 0.0335), V (0, 0.251, 0.968)
    point P1 (0, 0)
    intersected point E1 (0, 0) from Line41
    coincidence: E1 P1
  Hole52: placed by Sketch56, at (11500.5667, 35.7169, 3622.0475) direction (0.1335, 0.9593, -0.2488), diameter 7.7089, through (limit type 6)
  Sketch57 on {plane type Tangent, Support face of Mirror1, RefPoint {point type OnSurface, Support face of Mirror1, RefPoint {point stored without definition}, Length 0, Direction (0, -251.4453, -967.8715)}}, origin (11533.7929, 37.6908, 3647.4847), H (0.991, -0.1295, 0.0336), V (0, 0.2514, 0.9679)
    point P1 (0, 0)
    intersected point E1 (0, 0) from Line43
    coincidence: E1 P1
  Hole53: placed by Sketch57, at (11533.7929, 37.6908, 3647.4847) direction (0.1338, 0.9592, -0.2492), diameter 7.7089, through (limit type 6)
  Sketch58 on {plane type Tangent, Support face of Mirror1, RefPoint {point type OnSurface, Support face of Mirror1, RefPoint {point stored without definition}, Length 0, Direction (0, -248.3602, -968.6678)}}, origin (11500.5648, 47.6608, 3668.1043), H (0.9909, -0.1302, 0.0334), V (0, 0.2484, 0.9687)
    point P1 (0, 0)
    intersected point E1 (0, 0) from Line44
    coincidence: E1 P1
  Hole54: placed by Sketch58, at (11500.5648, 47.6608, 3668.1043) direction (0.1344, 0.9599, -0.2461), diameter 7.7089, through (limit type 6)
  Sketch59 on {plane type Tangent, Support face of Mirror1, RefPoint {point type OnSurface, Support face of Mirror1, RefPoint {point stored without definition}, Length 0, Direction (0, -239.7025, -970.8464)}}, origin (11500.5607, 59.2543, 3714.2229), H (0.9907, -0.1324, 0.0327), V (0, 0.2397, 0.9708)
    point P1 (0, 0)
    intersected point E1 (0, 0) from Line45
    coincidence: E1 P1
  Hole55: placed by Sketch59, at (11500.5607, 59.2543, 3714.2229) direction (0.1364, 0.9618, -0.2375), diameter 7.7089, through (limit type 6)
  Sketch60 on {plane type Tangent, Support face of Mirror1, RefPoint {point type OnSurface, Support face of Mirror1, RefPoint {point stored without definition}, Length 0, Direction (0, -232.2993, -972.6444)}}, origin (11500.5561, 70.4796, 3760.4384), H (0.9904, -0.1348, 0.0322), V (0, 0.2323, 0.9726)
    point P1 (0, 0)
    intersected point E1 (0, 0) from Line48
    coincidence: E1 P1
  Hole56: placed by Sketch60, at (11500.5561, 70.4796, 3760.4384) direction (0.1385, 0.9633, -0.2301), diameter 7.7089, through (limit type 6)
  Sketch61 on {plane type Tangent, Support face of Mirror1, RefPoint {point type OnSurface, Support face of Mirror1, RefPoint {point stored without definition}, Length 0, Direction (0, -233.3083, -972.4028)}}, origin (11533.7634, 62.1656, 3745.6401), H (0.9904, -0.1344, 0.0323), V (0, 0.2333, 0.9724)
    point P1 (0, 0)
    intersected point E1 (0, 0) from Line47
    coincidence: E1 P1
  Hole57: placed by Sketch61, at (11533.7634, 62.1656, 3745.6401) direction (0.1382, 0.9631, -0.2311), diameter 7.7089, through (limit type 6)
  Sketch62 on {plane type Tangent, Support face of Mirror1, RefPoint {point type OnSurface, Support face of Mirror1, RefPoint {point stored without definition}, Length 0, Direction (0, -224.7151, -974.4245)}}, origin (11533.7466, 73.7581, 3794.8771), H (0.99, -0.1372, 0.0316), V (0, 0.2247, 0.9744)
    point P1 (0, 0)
    intersected point E1 (0, 0) from Line50
    coincidence: E1 P1
  Hole58: placed by Sketch62, at (11533.7466, 73.7581, 3794.8771) direction (0.1408, 0.9647, -0.2225), diameter 7.7089, through (limit type 6)
  Sketch63 on {plane type Tangent, Support face of Mirror1, RefPoint {point type OnSurface, Support face of Mirror1, RefPoint {point stored without definition}, Length 0, Direction (0, -223.9493, -974.6008)}}, origin (11500.5521, 81.3346, 3806.738), H (0.99, -0.1373, 0.0316), V (0, 0.2239, 0.9746)
    point P1 (0, 0)
    intersected point E1 (0, 0) from Line49
    coincidence: E1 P1
  Hole59: placed by Sketch63, at (11500.5521, 81.3346, 3806.738) direction (0.1409, 0.9649, -0.2217), diameter 7.7089, through (limit type 6)
  Sketch64 on {plane type Tangent, Support face of Mirror1, RefPoint {point type OnSurface, Support face of Mirror1, RefPoint {point stored without definition}, Length 0, Direction (0, -214.3624, -976.7542)}}, origin (11500.5481, 91.7591, 3853.1309), H (0.9897, -0.14, 0.0307), V (0, 0.2144, 0.9768)
    point P1 (0, 0)
    intersected point E1 (0, 0) from Line51
    coincidence: E1 P1
  Hole60: placed by Sketch64, at (11500.5481, 91.7591, 3853.1309) direction (0.1434, 0.9667, -0.2121), diameter 7.7089, through (limit type 6)
  Sketch65 on {plane type Tangent, Support face of Mirror1, RefPoint {point type OnSurface, Support face of Mirror1, RefPoint {point stored without definition}, Length 0, Direction (0, -214.7234, -976.6749)}}, origin (11533.7295, 84.8777, 3844.2167), H (0.9897, -0.1401, 0.0308), V (0, 0.2147, 0.9767)
    point P1 (0, 0)
    intersected point E1 (0, 0) from Line52
    coincidence: E1 P1
  Hole61: placed by Sketch65, at (11533.7295, 84.8777, 3844.2167) direction (0.1435, 0.9666, -0.2125), diameter 7.7089, through (limit type 6)
  Sketch66 on {plane type Tangent, Support face of Mirror1, RefPoint {point type OnSurface, Support face of Mirror1, RefPoint {point stored without definition}, Length 0, Direction (0, -204.7685, -978.8104)}}, origin (11500.5433, 101.7214, 3899.6256), H (0.9893, -0.1426, 0.0298), V (0, 0.2048, 0.9788)
    point P1 (0, 0)
    intersected point E1 (0, 0) from Line54
    coincidence: E1 P1
  Hole62: placed by Sketch66, at (11500.5433, 101.7214, 3899.6256) direction (0.1457, 0.9684, -0.2026), diameter 7.7089, through (limit type 6)
  Sketch67 on {plane type Tangent, Support face of Mirror1, RefPoint {point type OnSurface, Support face of Mirror1, RefPoint {point stored without definition}, Length 0, Direction (0, -204.5244, -978.8615)}}, origin (11533.7109, 95.4795, 3893.6695), H (0.9893, -0.1429, 0.0299), V (0, 0.2045, 0.9789)
    point P1 (0, 0)
    intersected point E1 (0, 0) from Line53
    coincidence: E1 P1
  Hole63: placed by Sketch67, at (11533.7109, 95.4795, 3893.6695) direction (0.146, 0.9684, -0.2023), diameter 7.7089, through (limit type 6)
  Sketch68 on {plane type Tangent, Support face of Mirror1, RefPoint {point type OnSurface, Support face of Mirror1, RefPoint {point stored without definition}, Length 0, Direction (0, -196.4609, -980.5117)}}, origin (11500.5392, 111.257, 3946.2153), H (0.989, -0.145, 0.029), V (0, 0.1965, 0.9805)
    point P1 (0, 0)
    intersected point E1 (0, 0) from Line55
    coincidence: E1 P1
  Hole64: placed by Sketch68, at (11500.5392, 111.257, 3946.2153) direction (0.1479, 0.9697, -0.1943), diameter 7.7089, through (limit type 6)
  Sketch69 on {plane type Tangent, Support face of Mirror1, RefPoint {point type OnSurface, Support face of Mirror1, RefPoint {point stored without definition}, Length 0, Direction (0, -195.6636, -980.6711)}}, origin (11533.6954, 105.5966, 3943.2297), H (0.9889, -0.1455, 0.029), V (0, 0.1957, 0.9807)
    point P1 (0, 0)
    intersected point E1 (0, 0) from Line56
    coincidence: E1 P1
  Hole65: placed by Sketch69, at (11533.6954, 105.5966, 3943.2297) direction (0.1483, 0.9698, -0.1935), diameter 7.7089, through (limit type 6)
  Sketch70 on {plane type Tangent, Support face of Mirror1, RefPoint {point type OnSurface, Support face of Mirror1, RefPoint {point stored without definition}, Length 0, Direction (0, -189.4221, -981.8957)}}, origin (11500.5367, 120.4291, 3992.8835), H (0.9887, -0.1471, 0.0284), V (0, 0.1894, 0.9819)
    point P1 (0, 0)
    intersected point E1 (0, 0) from Line57
    coincidence: E1 P1
  Hole66: placed by Sketch70, at (11500.5367, 120.4291, 3992.8835) direction (0.1498, 0.9708, -0.1873), diameter 7.7089, through (limit type 6)
  Sketch71 on {plane type Tangent, Support face of Mirror1, RefPoint {point type OnSurface, Support face of Mirror1, RefPoint {point stored without definition}, Length 0, Direction (0, -188.2022, -982.1303)}}, origin (11533.6814, 115.3027, 3992.8785), H (0.9886, -0.1478, 0.0283), V (0, 0.1882, 0.9821)
    point P1 (0, 0)
    intersected point E1 (0, 0) from Line58
    coincidence: E1 P1
  Hole67: placed by Sketch71, at (11533.6814, 115.3027, 3992.8785) direction (0.1504, 0.971, -0.1861), diameter 7.7089, through (limit type 6)
  Sketch72 on {plane type Tangent, Support face of Mirror1, RefPoint {point type OnSurface, Support face of Mirror1, RefPoint {point stored without definition}, Length 0, Direction (0, -183.284, -983.06)}}, origin (11500.5328, 129.6785, 4041.6701), H (0.9884, -0.1492, 0.0278), V (0, 0.1833, 0.9831)
    point P1 (0, 0)
    intersected point E1 (0, 0) from Line60
    coincidence: E1 P1
  Hole68: placed by Sketch72, at (11500.5328, 129.6785, 4041.6701) direction (0.1518, 0.9717, -0.1812), diameter 7.7089, through (limit type 6)
  Sketch73 on {plane type Tangent, Support face of Mirror1, RefPoint {point type OnSurface, Support face of Mirror1, RefPoint {point stored without definition}, Length 0, Direction (0, -181.9836, -983.3016)}}, origin (11533.6674, 124.6646, 4042.5986), H (0.9883, -0.1499, 0.0277), V (0, 0.182, 0.9833)
    point P1 (0, 0)
    intersected point E1 (0, 0) from Line59
    coincidence: E1 P1
  Hole69: placed by Sketch73, at (11533.6674, 124.6646, 4042.5986) direction (0.1524, 0.9718, -0.1799), diameter 7.7089, through (limit type 6)
  Sketch74 on {plane type Tangent, Support face of Mirror1, RefPoint {point type OnSurface, Support face of Mirror1, RefPoint {point stored without definition}, Length 0, Direction (0, -178.0476, -984.0219)}}, origin (11500.5286, 138.8222, 4091.4663), H (0.9881, -0.1512, 0.0274), V (0, 0.178, 0.984)
    point P1 (0, 0)
    intersected point E1 (0, 0) from Line61
    coincidence: E1 P1
  Hole70: placed by Sketch74, at (11500.5286, 138.8222, 4091.4663) direction (0.1537, 0.9723, -0.1759), diameter 7.7089, through (limit type 6)
  Sketch75 on {plane type Tangent, Support face of Mirror1, RefPoint {point type OnSurface, Support face of Mirror1, RefPoint {point stored without definition}, Length 0, Direction (0, -176.7535, -984.2552)}}, origin (11533.6539, 133.7389, 4092.3767), H (0.988, -0.152, 0.0273), V (0, 0.1768, 0.9843)
    point P1 (0, 0)
    intersected point E1 (0, 0) from Line62
    coincidence: E1 P1
  Hole71: placed by Sketch75, at (11533.6539, 133.7389, 4092.3767) direction (0.1544, 0.9725, -0.1746), diameter 7.7089, through (limit type 6)
  Sketch76 on {plane type Tangent, Support face of Mirror1, RefPoint {point type OnSurface, Support face of Mirror1, RefPoint {point stored without definition}, Length 0, Direction (0, -173.5999, -984.8163)}}, origin (11500.5259, 147.7209, 4141.3035), H (0.9878, -0.1533, 0.027), V (0, 0.1736, 0.9848)
    point P1 (0, 0)
    intersected point E1 (0, 0) from Line63
    coincidence: E1 P1
  Hole72: placed by Sketch76, at (11500.5259, 147.7209, 4141.3035) direction (0.1556, 0.9728, -0.1715), diameter 7.7089, through (limit type 6)
  Sketch77 on {plane type Tangent, Support face of Mirror1, RefPoint {point type OnSurface, Support face of Mirror1, RefPoint {point stored without definition}, Length 0, Direction (0, -172.2768, -985.0486)}}, origin (11533.6404, 142.5689, 4142.202), H (0.9877, -0.154, 0.0269), V (0, 0.1723, 0.985)
    point P1 (0, 0)
    intersected point E1 (0, 0) from Line64
    coincidence: E1 P1
  Hole73: placed by Sketch77, at (11533.6404, 142.5689, 4142.202) direction (0.1563, 0.9729, -0.1702), diameter 7.7089, through (limit type 6)
  Sketch78 on {plane type Tangent, Support face of Mirror1, RefPoint {point type OnSurface, Support face of Mirror1, RefPoint {point stored without definition}, Length 0, Direction (0, -169.7864, -985.4809)}}, origin (11500.5223, 156.4103, 4191.1734), H (0.9875, -0.1554, 0.0268), V (0, 0.1698, 0.9855)
    point P1 (0, 0)
    intersected point E1 (0, 0) from Line65
    coincidence: E1 P1
  Hole74: placed by Sketch78, at (11500.5223, 156.4103, 4191.1734) direction (0.1577, 0.9732, -0.1677), diameter 7.7089, through (limit type 6)
  Sketch79 on {plane type Tangent, Support face of Mirror1, RefPoint {point type OnSurface, Support face of Mirror1, RefPoint {point stored without definition}, Length 0, Direction (0, -168.4055, -985.7178)}}, origin (11533.6259, 151.1888, 4192.0667), H (0.9874, -0.1561, 0.0267), V (0, 0.1684, 0.9857)
    point P1 (0, 0)
    intersected point E1 (0, 0) from Line66
    coincidence: E1 P1
  Hole75: placed by Sketch79, at (11533.6259, 151.1888, 4192.0667) direction (0.1584, 0.9733, -0.1663), diameter 7.7089, through (limit type 6)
